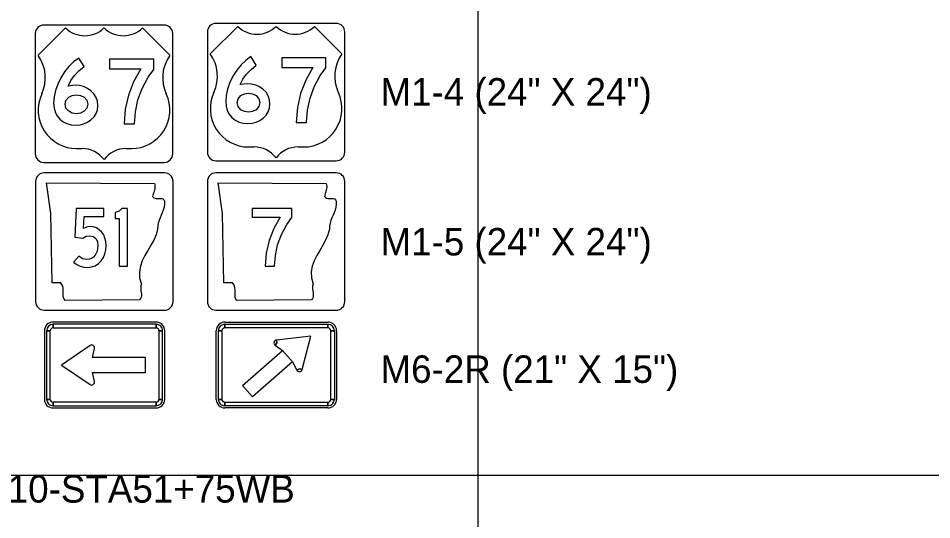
# Model space of a CAD drawing. Extents: x 1001568 to 1002149, y 1840825 to 1841423.
# Drawn here: x 1001928.96 to 1001942.25, y 1841194.82 to 1841202.12 of the extents above; entities that cross this region are included whole.
import ezdxf

# ---------------------------------------------------------------- set-up
doc = ezdxf.new("R2010")
doc.units = 0
for name, color, linetype in [('40', 7, 'Continuous'), ('R_No Plot', 7, 'Continuous'), ('SIGNS', 7, 'Continuous')]:
    doc.layers.add(name, color=color, linetype=linetype)

msp = doc.modelspace()

# ---------------------------------------------------------------- linework, layer by layer
at = {"layer": 'R_No Plot'}
for p, q in [((1001935.65, 1841210.667), (1001935.65, 1841148.127)), ((1001886.411, 1841195.469), (1001982.133, 1841195.469))]:
    msp.add_line(p, q, dxfattribs=at)
at = {"layer": 'SIGNS'}
for p, q in [((1001931.085, 1841202.025), (1001929.335, 1841202.025)), ((1001933.589, 1841202.048), (1001931.839, 1841202.048)), ((1001929.21, 1841201.9), (1001929.21, 1841200.15)), ((1001929.651, 1841201.983), (1001929.252, 1841201.584)), ((1001931.168, 1841201.584), (1001930.769, 1841201.983)), ((1001931.21, 1841200.15), (1001931.21, 1841201.9)), ((1001931.714, 1841201.923), (1001931.714, 1841200.173)), ((1001932.155, 1841202.006), (1001931.756, 1841201.607)), ((1001933.672, 1841201.607), (1001933.273, 1841202.006)), ((1001933.714, 1841200.173), (1001933.714, 1841201.923)), ((1001929.21, 1841200.15), (1001929.21, 1841200.15)), ((1001929.811, 1841200.226), (1001929.891, 1841200.226)), ((1001930.529, 1841200.226), (1001930.609, 1841200.226)), ((1001931.714, 1841200.173), (1001931.714, 1841200.173)), ((1001932.315, 1841200.249), (1001932.394, 1841200.249)), ((1001933.033, 1841200.249), (1001933.113, 1841200.249)), ((1001929.335, 1841200.025), (1001931.085, 1841200.025)), ((1001931.839, 1841200.048), (1001933.589, 1841200.048)), ((1001931.089, 1841199.872), (1001929.339, 1841199.872)), ((1001933.589, 1841199.872), (1001931.839, 1841199.872)), ((1001929.214, 1841199.747), (1001929.214, 1841197.997)), ((1001931.214, 1841197.997), (1001931.214, 1841199.747)), ((1001931.714, 1841199.747), (1001931.714, 1841197.997)), ((1001933.714, 1841197.997), (1001933.714, 1841199.747)), ((1001929.214, 1841197.997), (1001929.214, 1841197.997)), ((1001931.714, 1841197.997), (1001931.714, 1841197.997)), ((1001929.339, 1841197.872), (1001931.089, 1841197.872)), ((1001931.839, 1841197.872), (1001933.589, 1841197.872)), ((1001930.968, 1841197.698), (1001929.468, 1841197.698)), ((1001929.468, 1841197.615), (1001929.468, 1841197.667)), ((1001930.968, 1841197.667), (1001930.968, 1841197.615)), ((1001931.968, 1841197.698), (1001933.468, 1841197.698)), ((1001931.968, 1841197.667), (1001931.968, 1841197.615)), ((1001933.468, 1841197.615), (1001933.468, 1841197.667)), ((1001929.343, 1841197.573), (1001929.343, 1841196.573)), ((1001929.374, 1841197.573), (1001929.426, 1841197.573)), ((1001931.009, 1841197.573), (1001931.062, 1841197.573)), ((1001931.093, 1841196.573), (1001931.093, 1841197.573)), ((1001931.843, 1841196.573), (1001931.843, 1841197.573)), ((1001931.926, 1841197.573), (1001931.874, 1841197.573)), ((1001933.562, 1841197.573), (1001933.51, 1841197.573)), ((1001933.593, 1841197.573), (1001933.593, 1841196.573)), ((1001930.008, 1841197.359), (1001929.593, 1841197.073)), ((1001932.7, 1841197.362), (1001932.724, 1841197.396)), ((1001932.724, 1841197.396), (1001932.718, 1841197.437)), ((1001930.041, 1841197.183), (1001930.071, 1841197.314)), ((1001930.812, 1841197.183), (1001930.041, 1841197.183)), ((1001930.812, 1841197.183), (1001930.812, 1841197.183)), ((1001930.812, 1841196.964), (1001930.812, 1841197.183)), ((1001929.593, 1841197.073), (1001929.593, 1841197.073)), ((1001929.593, 1841197.073), (1001930.008, 1841196.788)), ((1001930.071, 1841196.833), (1001930.041, 1841196.964)), ((1001930.041, 1841196.964), (1001930.812, 1841196.964)), ((1001933.052, 1841197.018), (1001933.016, 1841196.999)), ((1001933.092, 1841197.006), (1001933.052, 1841197.018)), ((1001929.426, 1841196.573), (1001929.374, 1841196.573)), ((1001931.062, 1841196.573), (1001931.009, 1841196.573)), ((1001931.874, 1841196.573), (1001931.926, 1841196.573)), ((1001933.51, 1841196.573), (1001933.562, 1841196.573)), ((1001929.468, 1841196.48), (1001929.468, 1841196.532)), ((1001929.468, 1841196.448), (1001930.968, 1841196.448)), ((1001930.968, 1841196.532), (1001930.968, 1841196.48)), ((1001931.968, 1841196.532), (1001931.968, 1841196.48)), ((1001933.468, 1841196.448), (1001931.968, 1841196.448)), ((1001933.468, 1841196.48), (1001933.468, 1841196.532))]:
    msp.add_line(p, q, dxfattribs=at)
for points in [[(1001929.335, 1841202.025), (1001929.335, 1841202.025)], [(1001931.085, 1841202.025), (1001931.085, 1841202.025)], [(1001931.839, 1841202.048), (1001931.839, 1841202.048)], [(1001933.589, 1841202.048), (1001933.589, 1841202.048)], [(1001929.21, 1841201.9), (1001929.21, 1841201.9)], [(1001931.714, 1841201.923), (1001931.714, 1841201.923)], [(1001929.919, 1841201.42), (1001929.843, 1841201.544), (1001929.768, 1841201.489), (1001929.7, 1841201.423), (1001929.637, 1841201.345), (1001929.582, 1841201.257), (1001929.536, 1841201.164), (1001929.503, 1841201.071), (1001929.483, 1841200.978), (1001929.477, 1841200.887), (1001929.482, 1841200.819), (1001929.499, 1841200.758), (1001929.528, 1841200.704), (1001929.567, 1841200.656), (1001929.616, 1841200.617), (1001929.671, 1841200.589), (1001929.732, 1841200.573), (1001929.8, 1841200.567), (1001929.861, 1841200.572), (1001929.918, 1841200.586), (1001929.971, 1841200.61), (1001930.02, 1841200.644), (1001930.064, 1841200.688), (1001930.096, 1841200.736), (1001930.115, 1841200.791), (1001930.121, 1841200.85), (1001930.115, 1841200.914), (1001930.096, 1841200.972), (1001930.063, 1841201.023), (1001930.019, 1841201.069), (1001929.968, 1841201.103), (1001929.913, 1841201.128), (1001929.853, 1841201.143), (1001929.788, 1841201.148), (1001929.686, 1841201.137), (1001929.729, 1841201.215), (1001929.781, 1841201.288), (1001929.845, 1841201.356), (1001929.919, 1841201.42)], [(1001932.423, 1841201.442), (1001932.347, 1841201.567), (1001932.272, 1841201.511), (1001932.204, 1841201.445), (1001932.141, 1841201.368), (1001932.086, 1841201.28), (1001932.04, 1841201.186), (1001932.007, 1841201.093), (1001931.987, 1841201.001), (1001931.981, 1841200.91), (1001931.986, 1841200.842), (1001932.003, 1841200.781), (1001932.031, 1841200.727), (1001932.071, 1841200.679), (1001932.12, 1841200.64), (1001932.175, 1841200.612), (1001932.236, 1841200.596), (1001932.304, 1841200.59), (1001932.365, 1841200.595), (1001932.422, 1841200.609), (1001932.475, 1841200.633), (1001932.524, 1841200.667), (1001932.568, 1841200.71), (1001932.6, 1841200.759), (1001932.619, 1841200.813), (1001932.625, 1841200.873), (1001932.619, 1841200.937), (1001932.6, 1841200.994), (1001932.567, 1841201.046), (1001932.523, 1841201.092), (1001932.472, 1841201.126), (1001932.417, 1841201.151), (1001932.357, 1841201.165), (1001932.291, 1841201.17), (1001932.19, 1841201.16), (1001932.232, 1841201.237), (1001932.285, 1841201.31), (1001932.349, 1841201.378), (1001932.423, 1841201.442)], [(1001929.643, 1841200.872), (1001929.656, 1841200.928), (1001929.696, 1841200.974), (1001929.748, 1841201.001), (1001929.807, 1841201.01), (1001929.866, 1841201.001), (1001929.919, 1841200.974), (1001929.96, 1841200.929), (1001929.974, 1841200.872), (1001929.96, 1841200.814), (1001929.919, 1841200.769), (1001929.866, 1841200.742), (1001929.807, 1841200.733), (1001929.748, 1841200.742), (1001929.696, 1841200.769), (1001929.656, 1841200.814), (1001929.643, 1841200.872)], [(1001932.147, 1841200.895), (1001932.16, 1841200.951), (1001932.2, 1841200.997), (1001932.252, 1841201.023), (1001932.311, 1841201.032), (1001932.37, 1841201.023), (1001932.423, 1841200.997), (1001932.464, 1841200.951), (1001932.478, 1841200.895), (1001932.464, 1841200.837), (1001932.423, 1841200.791), (1001932.37, 1841200.764), (1001932.311, 1841200.756), (1001932.252, 1841200.764), (1001932.2, 1841200.791), (1001932.16, 1841200.837), (1001932.147, 1841200.895)], [(1001929.335, 1841200.025), (1001929.335, 1841200.025)], [(1001931.085, 1841200.025), (1001931.085, 1841200.025)], [(1001931.839, 1841200.048), (1001931.839, 1841200.048)], [(1001933.589, 1841200.048), (1001933.589, 1841200.048)], [(1001929.339, 1841199.872), (1001929.339, 1841199.872)], [(1001931.089, 1841199.872), (1001931.089, 1841199.872)], [(1001931.839, 1841199.872), (1001931.839, 1841199.872)], [(1001933.589, 1841199.872), (1001933.589, 1841199.872)], [(1001929.214, 1841199.747), (1001929.214, 1841199.747)], [(1001931.714, 1841199.747), (1001931.714, 1841199.747)], [(1001929.339, 1841197.872), (1001929.339, 1841197.872)], [(1001931.089, 1841197.872), (1001931.089, 1841197.872)], [(1001931.839, 1841197.872), (1001931.839, 1841197.872)], [(1001933.589, 1841197.872), (1001933.589, 1841197.872)]]:
    msp.add_lwpolyline(points, dxfattribs=at)
for points in [[(1001930.503, 1841200.586), (1001930.655, 1841200.586), (1001930.667, 1841200.762), (1001930.704, 1841200.935), (1001930.766, 1841201.103), (1001930.852, 1841201.266), (1001930.936, 1841201.378), (1001930.936, 1841201.526), (1001930.291, 1841201.526), (1001930.291, 1841201.385), (1001930.745, 1841201.385), (1001930.641, 1841201.2), (1001930.566, 1841201.006), (1001930.519, 1841200.801)], [(1001933.007, 1841200.608), (1001933.158, 1841200.608), (1001933.171, 1841200.785), (1001933.208, 1841200.958), (1001933.27, 1841201.125), (1001933.356, 1841201.289), (1001933.44, 1841201.401), (1001933.44, 1841201.548), (1001932.795, 1841201.548), (1001932.795, 1841201.407), (1001933.249, 1841201.407), (1001933.145, 1841201.223), (1001933.069, 1841201.029), (1001933.023, 1841200.824)], [(1001930.944, 1841199.718), (1001930.949, 1841199.699), (1001930.95, 1841199.679), (1001930.95, 1841199.66), (1001930.947, 1841199.641), (1001930.943, 1841199.622), (1001930.938, 1841199.603), (1001930.933, 1841199.584), (1001930.927, 1841199.566), (1001930.922, 1841199.547), (1001930.917, 1841199.529), (1001930.931, 1841199.513), (1001930.948, 1841199.504), (1001930.968, 1841199.5), (1001930.989, 1841199.499), (1001931.011, 1841199.5), (1001931.031, 1841199.5), (1001931.05, 1841199.498), (1001931.067, 1841199.492), (1001931.08, 1841199.48), (1001931.088, 1841199.46), (1001931.089, 1841199.414), (1001931.083, 1841199.371), (1001931.072, 1841199.331), (1001931.058, 1841199.292), (1001931.042, 1841199.254), (1001931.026, 1841199.216), (1001931.011, 1841199.178), (1001930.999, 1841199.138), (1001930.991, 1841199.097), (1001930.989, 1841199.053), (1001930.967, 1841198.971), (1001930.933, 1841198.892), (1001930.892, 1841198.817), (1001930.848, 1841198.742), (1001930.805, 1841198.667), (1001930.767, 1841198.591), (1001930.739, 1841198.513), (1001930.725, 1841198.43), (1001930.728, 1841198.343), (1001930.754, 1841198.249), (1001930.746, 1841198.226), (1001930.744, 1841198.202), (1001930.744, 1841198.178), (1001930.747, 1841198.154), (1001930.751, 1841198.13), (1001930.753, 1841198.107), (1001930.754, 1841198.084), (1001930.751, 1841198.062), (1001930.742, 1841198.041), (1001930.727, 1841198.021), (1001929.643, 1841198.011), (1001929.629, 1841198.031), (1001929.62, 1841198.055), (1001929.616, 1841198.081), (1001929.616, 1841198.109), (1001929.617, 1841198.139), (1001929.617, 1841198.168), (1001929.615, 1841198.197), (1001929.609, 1841198.224), (1001929.598, 1841198.248), (1001929.58, 1841198.269), (1001929.454, 1841198.269), (1001929.436, 1841199.281), (1001929.372, 1841199.728), (1001930.944, 1841199.718), (1001930.944, 1841199.718)], [(1001933.444, 1841199.718), (1001933.449, 1841199.699), (1001933.45, 1841199.679), (1001933.45, 1841199.66), (1001933.447, 1841199.641), (1001933.443, 1841199.622), (1001933.438, 1841199.603), (1001933.433, 1841199.584), (1001933.427, 1841199.566), (1001933.422, 1841199.547), (1001933.417, 1841199.529), (1001933.431, 1841199.513), (1001933.448, 1841199.504), (1001933.468, 1841199.5), (1001933.489, 1841199.499), (1001933.511, 1841199.5), (1001933.531, 1841199.5), (1001933.55, 1841199.498), (1001933.567, 1841199.492), (1001933.58, 1841199.48), (1001933.588, 1841199.46), (1001933.589, 1841199.414), (1001933.583, 1841199.371), (1001933.572, 1841199.331), (1001933.558, 1841199.292), (1001933.542, 1841199.254), (1001933.526, 1841199.216), (1001933.511, 1841199.178), (1001933.499, 1841199.138), (1001933.491, 1841199.097), (1001933.489, 1841199.053), (1001933.467, 1841198.971), (1001933.433, 1841198.892), (1001933.392, 1841198.817), (1001933.348, 1841198.742), (1001933.305, 1841198.667), (1001933.267, 1841198.591), (1001933.239, 1841198.513), (1001933.225, 1841198.43), (1001933.228, 1841198.343), (1001933.254, 1841198.249), (1001933.246, 1841198.226), (1001933.244, 1841198.202), (1001933.244, 1841198.178), (1001933.247, 1841198.154), (1001933.251, 1841198.13), (1001933.253, 1841198.107), (1001933.254, 1841198.084), (1001933.251, 1841198.062), (1001933.242, 1841198.041), (1001933.227, 1841198.021), (1001932.143, 1841198.011), (1001932.129, 1841198.031), (1001932.12, 1841198.055), (1001932.116, 1841198.081), (1001932.116, 1841198.109), (1001932.117, 1841198.139), (1001932.117, 1841198.168), (1001932.115, 1841198.197), (1001932.109, 1841198.224), (1001932.098, 1841198.248), (1001932.08, 1841198.269), (1001931.954, 1841198.269), (1001931.936, 1841199.281), (1001931.872, 1841199.728), (1001933.444, 1841199.718), (1001933.444, 1841199.718)], [(1001929.764, 1841198.57), (1001929.812, 1841198.537), (1001929.862, 1841198.514), (1001929.914, 1841198.5), (1001929.969, 1841198.495), (1001930.028, 1841198.501), (1001930.081, 1841198.519), (1001930.128, 1841198.55), (1001930.169, 1841198.593), (1001930.2, 1841198.64), (1001930.222, 1841198.693), (1001930.235, 1841198.75), (1001930.239, 1841198.813), (1001930.236, 1841198.871), (1001930.224, 1841198.923), (1001930.205, 1841198.969), (1001930.178, 1841199.01), (1001930.141, 1841199.044), (1001930.099, 1841199.069), (1001930.05, 1841199.084), (1001929.995, 1841199.089), (1001929.954, 1841199.082), (1001929.91, 1841199.062), (1001929.919, 1841199.238), (1001930.206, 1841199.238), (1001930.206, 1841199.353), (1001929.806, 1841199.353), (1001929.785, 1841198.937), (1001929.902, 1841198.922), (1001929.951, 1841198.948), (1001930.003, 1841198.957), (1001930.056, 1841198.945), (1001930.094, 1841198.911), (1001930.113, 1841198.865), (1001930.12, 1841198.808), (1001930.11, 1841198.733), (1001930.08, 1841198.672), (1001930.055, 1841198.645), (1001930.027, 1841198.626), (1001929.993, 1841198.614), (1001929.956, 1841198.611), (1001929.899, 1841198.622), (1001929.845, 1841198.657)], [(1001930.429, 1841198.512), (1001930.552, 1841198.512), (1001930.552, 1841199.353), (1001930.47, 1841199.353), (1001930.432, 1841199.312), (1001930.374, 1841199.297), (1001930.374, 1841199.208), (1001930.429, 1841199.208)], [(1001932.556, 1841198.512), (1001932.692, 1841198.512), (1001932.703, 1841198.67), (1001932.736, 1841198.825), (1001932.792, 1841198.975), (1001932.87, 1841199.121), (1001932.944, 1841199.221), (1001932.944, 1841199.353), (1001932.367, 1841199.353), (1001932.367, 1841199.227), (1001932.774, 1841199.227), (1001932.68, 1841199.062), (1001932.613, 1841198.888), (1001932.571, 1841198.704)], [(1001930.968, 1841197.667), (1001929.468, 1841197.667), (1001929.468, 1841197.615), (1001930.968, 1841197.615), (1001930.968, 1841197.667), (1001930.968, 1841197.667)], [(1001931.968, 1841197.667), (1001933.468, 1841197.667), (1001933.468, 1841197.615), (1001931.968, 1841197.615), (1001931.968, 1841197.667), (1001931.968, 1841197.667)], [(1001929.374, 1841197.573), (1001929.374, 1841196.573), (1001929.426, 1841196.573), (1001929.426, 1841197.573), (1001929.374, 1841197.573), (1001929.374, 1841197.573)], [(1001931.062, 1841196.573), (1001931.062, 1841197.573), (1001931.009, 1841197.573), (1001931.009, 1841196.573), (1001931.062, 1841196.573), (1001931.062, 1841196.573)], [(1001931.874, 1841196.573), (1001931.874, 1841197.573), (1001931.926, 1841197.573), (1001931.926, 1841196.573), (1001931.874, 1841196.573), (1001931.874, 1841196.573)], [(1001933.218, 1841197.494), (1001932.718, 1841197.437), (1001932.724, 1841197.396), (1001932.7, 1841197.362), (1001932.809, 1841197.283), (1001932.952, 1841197.118), (1001933.016, 1841196.999), (1001933.052, 1841197.018), (1001933.092, 1841197.006), (1001933.218, 1841197.494)], [(1001933.562, 1841197.573), (1001933.562, 1841196.573), (1001933.51, 1841196.573), (1001933.51, 1841197.573), (1001933.562, 1841197.573), (1001933.562, 1841197.573)], [(1001932.37, 1841196.612), (1001932.227, 1841196.777), (1001932.809, 1841197.283), (1001932.952, 1841197.118), (1001932.37, 1841196.612)], [(1001929.468, 1841196.48), (1001930.968, 1841196.48), (1001930.968, 1841196.532), (1001929.468, 1841196.532), (1001929.468, 1841196.48), (1001929.468, 1841196.48)], [(1001933.468, 1841196.48), (1001931.968, 1841196.48), (1001931.968, 1841196.532), (1001933.468, 1841196.532), (1001933.468, 1841196.48), (1001933.468, 1841196.48)]]:
    msp.add_lwpolyline(points, close=True, dxfattribs=at)
for centre, radius, start, end in [((1001929.335, 1841201.9), 0.125, 90.0002, 179.9998), ((1001931.085, 1841201.9), 0.125, 0, 90), ((1001931.839, 1841201.923), 0.125, 90.0002, 179.9998), ((1001933.589, 1841201.923), 0.125, 0, 90), ((1001929.93, 1841202.268), 0.399, 225.5729, 314.4272), ((1001930.49, 1841202.268), 0.399, 225.5729, 314.4272), ((1001932.434, 1841202.291), 0.399, 225.5729, 314.4272), ((1001932.993, 1841202.291), 0.399, 225.5729, 314.4272), ((1001928.797, 1841201.258), 0.559, 334.9895, 35.6629), ((1001931.622, 1841201.258), 0.559, 144.3372, 205.01), ((1001931.301, 1841201.281), 0.559, 334.9895, 35.6629), ((1001934.126, 1841201.281), 0.559, 144.3372, 205.01), ((1001929.811, 1841200.785), 0.559, 154.9897, 270.0001), ((1001930.609, 1841200.785), 0.559, 270.0001, 25.0104), ((1001932.315, 1841200.808), 0.559, 154.9897, 270.0001), ((1001933.113, 1841200.808), 0.559, 270.0001, 25.0104), ((1001929.335, 1841200.15), 0.125, 180, 270), ((1001929.891, 1841199.827), 0.399, 36.8699, 90.0002), ((1001930.529, 1841199.827), 0.399, 90.0002, 143.13), ((1001931.085, 1841200.15), 0.125, 270.0001, 0.0003), ((1001931.839, 1841200.173), 0.125, 180, 270), ((1001932.394, 1841199.85), 0.399, 36.8699, 90.0002), ((1001933.033, 1841199.85), 0.399, 90.0002, 143.13), ((1001933.589, 1841200.173), 0.125, 270.0001, 0.0003), ((1001929.339, 1841199.747), 0.125, 90.0002, 179.9998), ((1001931.089, 1841199.747), 0.125, 0, 90), ((1001931.839, 1841199.747), 0.125, 90.0002, 179.9998), ((1001933.589, 1841199.747), 0.125, 0, 90), ((1001929.339, 1841197.997), 0.125, 180, 270), ((1001931.089, 1841197.997), 0.125, 270.0001, 0.0003), ((1001931.839, 1841197.997), 0.125, 180, 270), ((1001933.589, 1841197.997), 0.125, 270.0001, 0.0003), ((1001929.468, 1841197.573), 0.125, 90.0001, 180.0003), ((1001929.468, 1841197.573), 0.0937, 90.0001, 180.0003), ((1001930.968, 1841197.573), 0.125, 359.9998, 90.0001), ((1001930.968, 1841197.573), 0.0937, 359.9998, 90.0001), ((1001931.968, 1841197.573), 0.125, 89.9998, 180), ((1001931.968, 1841197.573), 0.0937, 89.9998, 180), ((1001933.468, 1841197.573), 0.125, 0.0002, 89.9998), ((1001933.468, 1841197.573), 0.0937, 0.0002, 89.9998), ((1001929.468, 1841197.573), 0.0417, 90.0001, 180.0003), ((1001930.968, 1841197.573), 0.0417, 359.9998, 90.0001), ((1001931.968, 1841197.573), 0.0417, 89.9998, 180), ((1001933.468, 1841197.573), 0.0417, 0.0002, 89.9998), ((1001930.03, 1841197.323), 0.0417, 347.0499, 122.2759), ((1001932.724, 1841197.396), 0.0417, 98.7244, 233.9504), ((1001933.052, 1841197.018), 0.0417, 208.0499, 343.2759), ((1001930.03, 1841196.823), 0.0417, 237.7244, 12.9504), ((1001929.468, 1841196.573), 0.125, 180, 270.0002), ((1001929.468, 1841196.573), 0.0937, 180, 270.0002), ((1001929.468, 1841196.573), 0.0417, 180, 270.0002), ((1001930.968, 1841196.573), 0.0937, 270.0002, 359.9998), ((1001930.968, 1841196.573), 0.0417, 270.0002, 359.9998), ((1001930.968, 1841196.573), 0.125, 270.0002, 359.9998), ((1001931.968, 1841196.573), 0.125, 179.9997, 269.9999), ((1001931.968, 1841196.573), 0.0937, 179.9997, 269.9999), ((1001931.968, 1841196.573), 0.0417, 179.9997, 269.9999), ((1001933.468, 1841196.573), 0.0937, 269.9999, 0.0002), ((1001933.468, 1841196.573), 0.0417, 269.9999, 0.0002), ((1001933.468, 1841196.573), 0.125, 269.9999, 0.0002)]:
    msp.add_arc(centre, radius, start, end, dxfattribs=at)

# ---------------------------------------------------------------- texts
at = {"layer": '40'}
for s, p in [('M1-4 (24" X 24")', (1001934.233, 1841200.852)), ('M1-5 (24" X 24")', (1001934.233, 1841198.669)), ('M6-2R (21" X 15")', (1001934.233, 1841196.813)), ('SS-CAD-10-STA51+75WB', (1001926.61, 1841195.069))]:
    msp.add_text(s, height=0.4, rotation=0, dxfattribs=at).set_placement(p)

doc.saveas('drawing.dxf')
